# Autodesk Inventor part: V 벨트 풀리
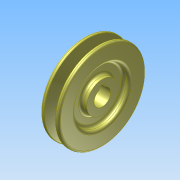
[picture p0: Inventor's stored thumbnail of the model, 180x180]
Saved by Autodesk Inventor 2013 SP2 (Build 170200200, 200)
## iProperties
Created: 2025-08
Part Number: V 벨트 풀리
Material: Generic
Document SubType Name: Modeling
Designer: i
Density: 1 g/cm^3
Author: i
변환 표준: STEP AP214IS
전처리기: Build: 200, Release: 2013 SP2 Update 6 - Date: Thu 07/17/2014
전송 단위: 밀리미터
불확실성: 0.01
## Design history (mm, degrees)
node "V 벨트 풀리1"
node "솔리드1"
node "기준1"
